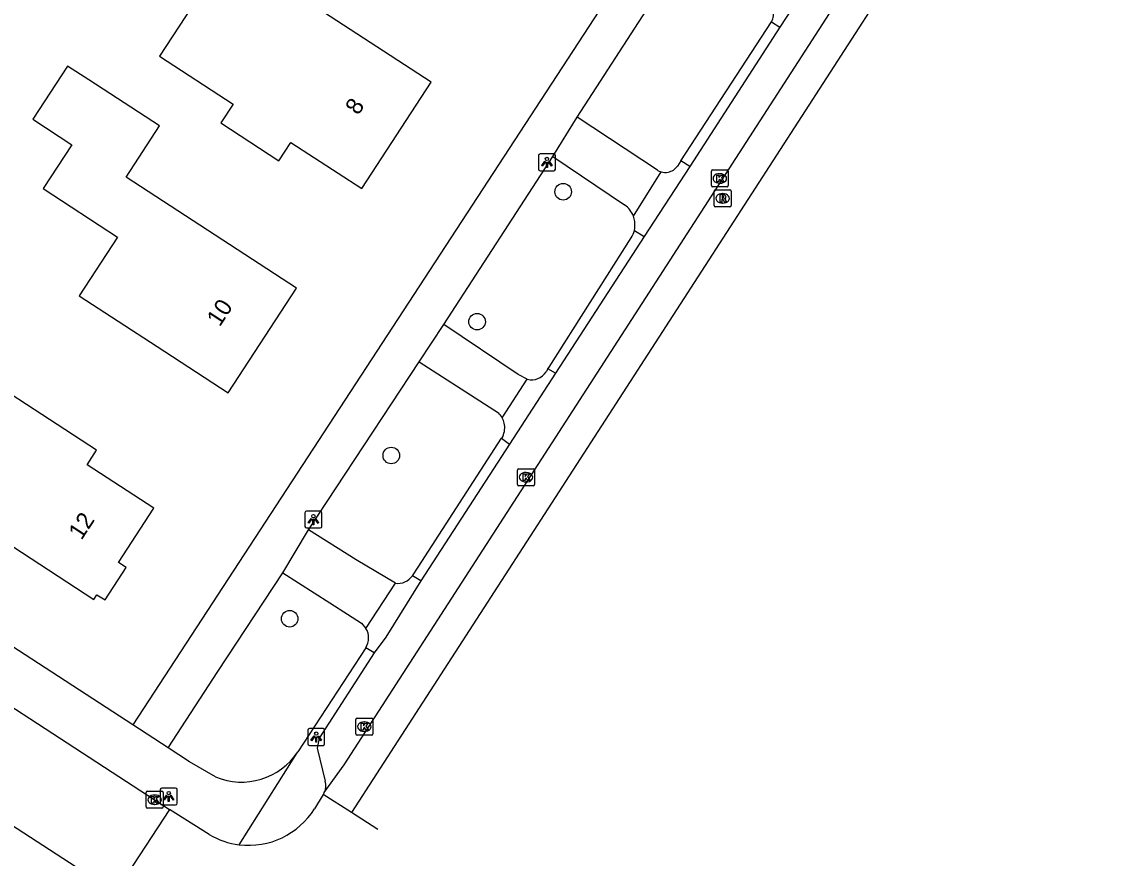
# Model space of a CAD drawing. Extents: x 161141 to 161601, y 381708 to 382245.
# Drawn here: x 161516.9 to 161581.4, y 382033 to 382082.4 of the extents above; entities that cross this region are included whole.
import ezdxf

# ---------------------------------------------------------------- set-up
doc = ezdxf.new("R2010")
doc.units = 0
for name, color, linetype in [('IMGEO_Boom', 7, 'Continuous'), ('IMGEO_Kolk', 7, 'Continuous'), ('IMGEO_Lichtpunt', 7, 'Continuous'), ('IMGEO_Pand', 7, 'Continuous'), ('IMGEO_Pand_nummerreeks', 7, 'Continuous'), ('IMGEO_Rijbaan_lokaal_gesloten', 7, 'Continuous'), ('IMGEO_Rijbaan_lokaal_open', 7, 'Continuous'), ('IMGEO_Rioolput', 7, 'Continuous'), ('IMGEO_Voetpad_open', 7, 'Continuous')]:
    doc.layers.add(name, color=color, linetype=linetype)

msp = doc.modelspace()

# ---------------------------------------------------------------- linework, layer by layer
at = {"layer": 'IMGEO_Boom'}
for centre in [(161548.856, 382072.342), (161543.772, 382064.666), (161538.702, 382056.761), (161532.7, 382047.114)]:
    msp.add_circle(centre, 0.489, dxfattribs=at)
at = {"layer": 'IMGEO_Kolk'}
for p, q in [((161557.611, 382072.704), (161557.611, 382073.556)), ((161557.686, 382073.63), (161558.538, 382073.63)), ((161558.612, 382073.556), (161558.612, 382072.704)), ((161558.122, 382072.85), (161558.097, 382072.85)), ((161558.099, 382073.41), (161558.124, 382073.41)), ((161558.538, 382072.63), (161557.686, 382072.63)), ((161546.165, 382055.049), (161546.165, 382055.901)), ((161546.24, 382055.975), (161547.092, 382055.975)), ((161546.653, 382055.755), (161546.678, 382055.755)), ((161547.166, 382055.901), (161547.166, 382055.049)), ((161547.092, 382054.975), (161546.24, 382054.975)), ((161546.676, 382055.195), (161546.651, 382055.195)), ((161536.682, 382041.24), (161537.534, 382041.24)), ((161536.607, 382040.314), (161536.607, 382041.166)), ((161537.095, 382041.02), (161537.12, 382041.02)), ((161537.608, 382041.166), (161537.608, 382040.314)), ((161537.534, 382040.24), (161536.682, 382040.24)), ((161537.118, 382040.46), (161537.093, 382040.46)), ((161524.224, 382035.995), (161524.224, 382036.847)), ((161524.299, 382036.921), (161525.151, 382036.921)), ((161524.712, 382036.701), (161524.737, 382036.701)), ((161525.225, 382036.847), (161525.225, 382035.995)), ((161524.735, 382036.141), (161524.71, 382036.141)), ((161525.151, 382035.921), (161524.299, 382035.921))]:
    msp.add_line(p, q, dxfattribs=at)
for points in [[(161557.611, 382072.704), (161557.611, 382073.556)], [(161557.686, 382073.63), (161558.538, 382073.63)], [(161558.612, 382073.556), (161558.612, 382072.704)], [(161557.932, 382073.33), (161558.055, 382073.33), (161558.055, 382073.179), (161558.185, 382073.33), (161558.349, 382073.33), (161558.203, 382073.179), (161558.356, 382072.93), (161558.204, 382072.93), (161558.119, 382073.094), (161558.055, 382073.027), (161558.055, 382072.93), (161557.932, 382072.93), (161557.932, 382073.33)], [(161558.538, 382072.63), (161557.686, 382072.63)], [(161546.165, 382055.049), (161546.165, 382055.901)], [(161546.24, 382055.975), (161547.092, 382055.975)], [(161546.486, 382055.675), (161546.609, 382055.675), (161546.609, 382055.524), (161546.739, 382055.675), (161546.903, 382055.675), (161546.757, 382055.524), (161546.91, 382055.275), (161546.758, 382055.275), (161546.673, 382055.439), (161546.609, 382055.372), (161546.609, 382055.275), (161546.486, 382055.275), (161546.486, 382055.675)], [(161547.166, 382055.901), (161547.166, 382055.049)], [(161547.092, 382054.975), (161546.24, 382054.975)], [(161536.682, 382041.24), (161537.534, 382041.24)], [(161536.607, 382040.314), (161536.607, 382041.166)], [(161536.928, 382040.94), (161537.051, 382040.94), (161537.051, 382040.789), (161537.181, 382040.94), (161537.345, 382040.94), (161537.199, 382040.789), (161537.352, 382040.54), (161537.2, 382040.54), (161537.115, 382040.704), (161537.051, 382040.637), (161537.051, 382040.54), (161536.928, 382040.54), (161536.928, 382040.94)], [(161537.608, 382041.166), (161537.608, 382040.314)], [(161537.534, 382040.24), (161536.682, 382040.24)], [(161524.224, 382035.995), (161524.224, 382036.847)], [(161524.299, 382036.921), (161525.151, 382036.921)], [(161525.225, 382036.847), (161525.225, 382035.995)], [(161524.545, 382036.621), (161524.668, 382036.621), (161524.668, 382036.47), (161524.798, 382036.621), (161524.962, 382036.621), (161524.816, 382036.47), (161524.969, 382036.221), (161524.817, 382036.221), (161524.732, 382036.385), (161524.668, 382036.318), (161524.668, 382036.221), (161524.545, 382036.221), (161524.545, 382036.621)], [(161525.151, 382035.921), (161524.299, 382035.921)]]:
    msp.add_lwpolyline(points, dxfattribs=at)
for centre, start, end in [((161557.688, 382073.554), 91.55205, 178.44795), ((161557.688, 382073.554), 91.55205, 178.44795), ((161558.536, 382073.554), 1.55205, 88.44795), ((161558.536, 382073.554), 1.55205, 88.44795), ((161557.688, 382072.706), 181.55205, 268.44795), ((161557.688, 382072.706), 181.55205, 268.44795), ((161558.536, 382072.706), 271.55205, 358.44795), ((161558.536, 382072.706), 271.55205, 358.44795), ((161546.242, 382055.899), 91.55205, 178.44795), ((161546.242, 382055.899), 91.55205, 178.44795), ((161547.09, 382055.899), 1.55205, 88.44795), ((161547.09, 382055.899), 1.55205, 88.44795), ((161546.242, 382055.051), 181.55205, 268.44795), ((161546.242, 382055.051), 181.55205, 268.44795), ((161547.09, 382055.051), 271.55205, 358.44795), ((161547.09, 382055.051), 271.55205, 358.44795), ((161536.684, 382041.164), 91.55205, 178.44795), ((161536.684, 382041.164), 91.55205, 178.44795), ((161537.532, 382041.164), 1.55205, 88.44795), ((161537.532, 382041.164), 1.55205, 88.44795), ((161536.684, 382040.316), 181.55205, 268.44795), ((161536.684, 382040.316), 181.55205, 268.44795), ((161537.532, 382040.316), 271.55205, 358.44795), ((161537.532, 382040.316), 271.55205, 358.44795), ((161524.301, 382036.845), 91.55205, 178.44795), ((161524.301, 382036.845), 91.55205, 178.44795), ((161525.149, 382036.845), 1.55205, 88.44795), ((161525.149, 382036.845), 1.55205, 88.44795), ((161524.301, 382035.997), 181.55205, 268.44795), ((161524.301, 382035.997), 181.55205, 268.44795), ((161525.149, 382035.997), 271.55205, 358.44795), ((161525.149, 382035.997), 271.55205, 358.44795)]:
    msp.add_arc(centre, 0.0765, start, end, dxfattribs=at)
for centre, major_axis, ratio, start_param, end_param in [((161558.098, 382073.13), (-0.387, 0.002), 0.722429, 4.712389, 7.853982), ((161558.123, 382073.13), (-0.39, 0.002), 0.717154, 1.570796, 4.712389), ((161546.652, 382055.475), (-0.387, 0.002), 0.722429, 4.712389, 7.853982), ((161546.677, 382055.475), (-0.39, 0.002), 0.717154, 1.570796, 4.712389), ((161537.094, 382040.74), (-0.387, 0.002), 0.722429, 4.712389, 7.853982), ((161537.119, 382040.74), (-0.39, 0.002), 0.717154, 1.570796, 4.712389), ((161524.711, 382036.421), (-0.387, 0.002), 0.722429, 4.712389, 7.853982), ((161524.736, 382036.421), (-0.39, 0.002), 0.717154, 1.570796, 4.712389)]:
    msp.add_ellipse(centre, major_axis=major_axis, ratio=ratio, start_param=start_param, end_param=end_param, dxfattribs=at)
at = {"layer": 'IMGEO_Lichtpunt'}
for p, q in [((161547.401, 382074.484), (161547.401, 382073.677)), ((161547.401, 382074.484), (161547.401, 382073.677)), ((161548.303, 382074.579), (161547.495, 382074.579)), ((161548.303, 382074.579), (161547.495, 382074.579)), ((161548.397, 382073.677), (161548.397, 382074.484)), ((161548.397, 382073.677), (161548.397, 382074.484)), ((161547.495, 382073.583), (161548.303, 382073.583)), ((161547.495, 382073.583), (161548.303, 382073.583)), ((161534.503, 382053.473), (161533.695, 382053.473)), ((161534.503, 382053.473), (161533.695, 382053.473)), ((161533.601, 382053.378), (161533.601, 382052.571)), ((161533.601, 382053.378), (161533.601, 382052.571)), ((161534.597, 382052.571), (161534.597, 382053.378)), ((161534.597, 382052.571), (161534.597, 382053.378)), ((161533.695, 382052.477), (161534.503, 382052.477)), ((161533.695, 382052.477), (161534.503, 382052.477)), ((161533.768, 382040.53), (161533.768, 382039.723)), ((161533.768, 382040.53), (161533.768, 382039.723)), ((161534.67, 382040.625), (161533.862, 382040.625)), ((161534.67, 382040.625), (161533.862, 382040.625)), ((161534.764, 382039.723), (161534.764, 382040.53)), ((161534.764, 382039.723), (161534.764, 382040.53)), ((161533.862, 382039.629), (161534.67, 382039.629)), ((161533.862, 382039.629), (161534.67, 382039.629)), ((161525.054, 382037.019), (161525.054, 382036.212)), ((161525.054, 382037.019), (161525.054, 382036.212)), ((161525.956, 382037.114), (161525.148, 382037.114)), ((161525.956, 382037.114), (161525.148, 382037.114)), ((161526.05, 382036.212), (161526.05, 382037.019)), ((161526.05, 382036.212), (161526.05, 382037.019)), ((161525.148, 382036.118), (161525.956, 382036.118)), ((161525.148, 382036.118), (161525.956, 382036.118))]:
    msp.add_line(p, q, dxfattribs=at)
for points in [[(161547.775, 382074.148), (161547.814, 382074.12), (161547.626, 382073.858), (161547.588, 382073.885), (161547.775, 382074.148)], [(161547.877, 382074.1), (161547.924, 382074.1), (161547.924, 382073.778), (161547.877, 382073.778), (161547.877, 382074.1)], [(161547.987, 382074.12), (161548.025, 382074.147), (161548.212, 382073.885), (161548.173, 382073.857), (161547.987, 382074.12)], [(161533.975, 382053.042), (161534.014, 382053.014), (161533.826, 382052.752), (161533.788, 382052.779), (161533.975, 382053.042)], [(161534.077, 382052.994), (161534.124, 382052.994), (161534.124, 382052.672), (161534.077, 382052.672), (161534.077, 382052.994)], [(161534.187, 382053.014), (161534.225, 382053.041), (161534.412, 382052.779), (161534.373, 382052.751), (161534.187, 382053.014)], [(161534.142, 382040.194), (161534.181, 382040.166), (161533.993, 382039.904), (161533.955, 382039.931), (161534.142, 382040.194)], [(161534.244, 382040.146), (161534.291, 382040.146), (161534.291, 382039.824), (161534.244, 382039.824), (161534.244, 382040.146)], [(161534.354, 382040.166), (161534.392, 382040.193), (161534.579, 382039.931), (161534.54, 382039.903), (161534.354, 382040.166)], [(161525.428, 382036.683), (161525.467, 382036.655), (161525.279, 382036.393), (161525.241, 382036.42), (161525.428, 382036.683)], [(161525.64, 382036.655), (161525.678, 382036.682), (161525.865, 382036.42), (161525.826, 382036.392), (161525.64, 382036.655)], [(161525.53, 382036.635), (161525.577, 382036.635), (161525.577, 382036.313), (161525.53, 382036.313), (161525.53, 382036.635)]]:
    msp.add_lwpolyline(points, dxfattribs=at)
for centre in [(161547.9, 382074.282), (161534.1, 382053.176), (161534.267, 382040.328), (161525.553, 382036.817)]:
    msp.add_circle(centre, 0.0994, dxfattribs=at)
for centre, start, end in [((161547.495, 382074.484), 90, 180), ((161547.495, 382074.484), 90, 180), ((161548.303, 382074.484), 0, 90), ((161548.303, 382074.484), 0, 90), ((161547.495, 382073.677), 180, 270), ((161547.495, 382073.677), 180, 270), ((161548.303, 382073.677), 270, 0), ((161548.303, 382073.677), 270, 360), ((161533.695, 382053.378), 90, 180), ((161533.695, 382053.378), 90, 180), ((161534.503, 382053.378), 0, 90), ((161534.503, 382053.378), 0, 90), ((161533.695, 382052.571), 180, 270), ((161533.695, 382052.571), 180, 270), ((161534.503, 382052.571), 270, 0), ((161534.503, 382052.571), 270, 360), ((161533.862, 382040.53), 90, 180), ((161533.862, 382040.53), 90, 180), ((161534.67, 382040.53), 0, 90), ((161534.67, 382040.53), 0, 90), ((161533.862, 382039.723), 180, 270), ((161533.862, 382039.723), 180, 270), ((161534.67, 382039.723), 270, 0), ((161534.67, 382039.723), 270, 360), ((161525.148, 382037.019), 90, 180), ((161525.148, 382037.019), 90, 180), ((161525.956, 382037.019), 0, 90), ((161525.956, 382037.019), 0, 90), ((161525.148, 382036.212), 180, 270), ((161525.148, 382036.212), 180, 270), ((161525.956, 382036.212), 270, 0), ((161525.956, 382036.212), 270, 360)]:
    msp.add_arc(centre, 0.0946, start, end, dxfattribs=at)
at = {"layer": 'IMGEO_Pand'}
for points in [[(161525.007, 382080.354), (161529.353, 382077.522), (161528.63, 382076.412), (161532.059, 382074.178), (161532.764, 382075.259), (161536.96, 382072.525), (161541.06, 382078.818), (161527.88, 382087.405), (161529.841, 382090.414), (161525.651, 382093.143), (161524.545, 382093.864), (161521.198, 382088.726), (161527.701, 382084.489), (161525.007, 382080.354)], [(161524.873, 382063.195), (161529.061, 382060.463), (161533.095, 382066.653), (161523.049, 382073.199), (161525.013, 382076.229), (161520.824, 382078.958), (161519.575, 382079.772), (161517.521, 382076.623), (161519.823, 382075.12), (161518.135, 382072.533), (161522.531, 382069.665), (161520.269, 382066.197), (161524.873, 382063.195)], [(161512.023, 382063.108), (161513.814, 382065.857), (161508.368, 382069.406), (161505.406, 382071.336), (161502.144, 382066.33), (161505.105, 382064.4), (161504.545, 382063.541), (161509.99, 382059.992), (161510.091, 382060.146), (161511.727, 382059.08), (161510.877, 382057.775), (161513.345, 382056.167), (161512.05, 382054.18), (161521.136, 382048.26), (161521.315, 382048.534), (161521.792, 382048.223), (161523.042, 382050.142), (161522.592, 382050.435), (161524.682, 382053.642), (161520.733, 382056.215), (161521.288, 382057.068), (161512.023, 382063.108)]]:
    msp.add_lwpolyline(points, dxfattribs=at)
at = {"layer": 'IMGEO_Rijbaan_lokaal_gesloten'}
for points in [[(161534.744, 382036.848), (161535.916, 382038.476), (161568.691, 382089.227), (161572.916, 382096.506)], [(161571.794, 382090.515), (161536.35, 382035.66)], [(161534.744, 382036.848), (161534.678, 382036.739)]]:
    msp.add_lwpolyline(points, dxfattribs=at)
at = {"layer": 'IMGEO_Rijbaan_lokaal_open'}
for points in [[(161385.362, 382126.757), (161388.136, 382124.895), (161391.361, 382122.845), (161399.992, 382117.288), (161403.197, 382115.21), (161416.21, 382106.739), (161420.597, 382103.968), (161426.931, 382099.82), (161440.905, 382090.804), (161444.055, 382088.754), (161453.24, 382082.778), (161460.192, 382078.284), (161467.324, 382073.702), (161468.287, 382073.003), (161471.488, 382070.983), (161480.028, 382065.466), (161483.251, 382063.426), (161485.554, 382061.86), (161494.669, 382055.998), (161498.469, 382053.534), (161512.078, 382044.654), (161521.765, 382038.348), (161525.596, 382035.854)], [(161522.385, 382030.943), (161510.796, 382038.454)], [(161534.678, 382036.739), (161534.166, 382035.893)], [(161536.35, 382035.66), (161534.678, 382036.739)], [(161525.596, 382035.854), (161522.385, 382030.943)], [(161527.949, 382034.358), (161525.596, 382035.854)], [(161537.898, 382034.67), (161536.35, 382035.66)]]:
    msp.add_lwpolyline(points, dxfattribs=at)
for centre, radius, start, end in [((161530.271, 382038.316), 4.587, 263.08011, 328.11728), ((161530.267, 382038.315), 4.586, 239.63862, 263.12265)]:
    msp.add_arc(centre, radius, start, end, dxfattribs=at)
at = {"layer": 'IMGEO_Rioolput'}
for p, q in [((161557.783, 382071.527), (161557.783, 382072.379)), ((161557.858, 382072.453), (161558.71, 382072.453)), ((161558.271, 382072.233), (161558.296, 382072.233)), ((161558.784, 382072.379), (161558.784, 382071.527)), ((161558.294, 382071.673), (161558.269, 382071.673)), ((161558.71, 382071.453), (161557.858, 382071.453))]:
    msp.add_line(p, q, dxfattribs=at)
for points in [[(161557.783, 382071.527), (161557.783, 382072.379)], [(161557.858, 382072.453), (161558.71, 382072.453)], [(161558.372, 382072.151), (161558.12, 382072.153), (161558.12, 382071.753)], [(161558.784, 382072.379), (161558.784, 382071.527)], [(161558.12, 382071.753), (161558.244, 382071.753), (161558.244, 382071.915), (161558.255, 382071.915)], [(161558.298, 382072.072), (161558.244, 382072.072), (161558.244, 382071.991)], [(161558.244, 382071.991), (161558.296, 382071.991)], [(161558.302, 382071.886), (161558.373, 382071.753), (161558.513, 382071.753), (161558.448, 382071.879)], [(161558.71, 382071.453), (161557.858, 382071.453)]]:
    msp.add_lwpolyline(points, dxfattribs=at)
for centre, radius, start, end in [((161557.86, 382072.377), 0.0765, 91.55205, 178.44795), ((161557.86, 382072.377), 0.0765, 91.55205, 178.44795), ((161558.371, 382072.041), 0.109, 350.36119, 89.41601), ((161558.708, 382072.377), 0.0765, 1.55205, 88.44795), ((161558.708, 382072.377), 0.0765, 1.55205, 88.44795), ((161557.86, 382071.529), 0.0765, 181.55205, 268.44795), ((161557.86, 382071.529), 0.0765, 181.55205, 268.44795), ((161558.254, 382071.862), 0.0533, 26.02933, 88.69889), ((161558.28, 382072.18), 0.19, 274.7715, 282.96867), ((161558.304, 382071.976), 0.0964, 77.00612, 93.18647), ((161558.318, 382072.033), 0.0378, 276.66336, 79.67722), ((161558.369, 382072.041), 0.112, 277.58423, 350.98172), ((161558.353, 382071.826), 0.108, 29.51342, 73.79051), ((161558.708, 382071.529), 0.0765, 271.55205, 358.44795), ((161558.708, 382071.529), 0.0765, 271.55205, 358.44795)]:
    msp.add_arc(centre, radius, start, end, dxfattribs=at)
for centre, major_axis, ratio, start_param, end_param in [((161558.27, 382071.953), (-0.387, 0.002), 0.722429, 4.712389, 7.853982), ((161558.295, 382071.953), (-0.39, 0.002), 0.717154, 1.570796, 4.712389)]:
    msp.add_ellipse(centre, major_axis=major_axis, ratio=ratio, start_param=start_param, end_param=end_param, dxfattribs=at)
at = {"layer": 'IMGEO_Voetpad_open'}
for points in [[(161523.437, 382040.853), (161500, 382056.07), (161450.498, 382088.211), (161408.789, 382114.947), (161389.855, 382127.317), (161365.175, 382143.293), (161365.084, 382143.565)], [(161581.409, 382129.761), (161561.628, 382099.383), (161523.437, 382040.853)], [(161549.678, 382076.751), (161556.061, 382086.613)], [(161564.239, 382086.032), (161561.667, 382082.065)], [(161555.805, 382074.166), (161561.16, 382082.381)], [(161561.667, 382082.065), (161556.335, 382073.842)], [(161561.16, 382082.381), (161561.667, 382082.065)], [(161548.238, 382074.428), (161549.678, 382076.751)], [(161554.422, 382073.613), (161549.678, 382076.751)], [(161541.805, 382064.505), (161548.238, 382074.428)], [(161548.238, 382074.428), (161552.488, 382071.564)], [(161555.805, 382074.166), (161555.605, 382073.86)], [(161556.335, 382073.842), (161555.805, 382074.166)], [(161553.007, 382070.898), (161554.64, 382073.517)], [(161556.335, 382073.842), (161553.645, 382069.693)], [(161547.959, 382061.886), (161548.022, 382061.982), (161552.884, 382069.618)], [(161553.645, 382069.693), (161548.411, 382061.62)], [(161553.065, 382070.06), (161553.645, 382069.693)], [(161540.355, 382062.295), (161541.805, 382064.505)], [(161546.737, 382061.267), (161546.19, 382061.555), (161541.805, 382064.505)], [(161533.813, 382052.367), (161540.355, 382062.295)], [(161540.355, 382062.295), (161545.028, 382059.277)], [(161547.959, 382061.886), (161547.846, 382061.711)], [(161548.411, 382061.62), (161547.959, 382061.886)], [(161545.258, 382058.983), (161546.737, 382061.267)], [(161548.411, 382061.62), (161545.69, 382057.424)], [(161539.95, 382049.657), (161540.282, 382050.166), (161545.221, 382057.781)], [(161545.69, 382057.424), (161540.456, 382049.35)], [(161545.289, 382057.886), (161545.221, 382057.781)], [(161545.221, 382057.781), (161545.69, 382057.424)], [(161532.291, 382049.829), (161533.813, 382052.367)], [(161538.946, 382049.208), (161536.622, 382050.604), (161533.813, 382052.367)], [(161525.518, 382039.495), (161528.456, 382043.995), (161532.291, 382049.829)], [(161532.291, 382049.829), (161535.064, 382048.048), (161536.938, 382046.844), (161537.207, 382046.547)], [(161540.456, 382049.35), (161539.95, 382049.657)], [(161537.207, 382046.547), (161538.946, 382049.208)], [(161540.456, 382049.35), (161538.374, 382046.036), (161537.696, 382045.093)], [(161537.192, 382045.404), (161533.184, 382039.253)], [(161537.696, 382045.093), (161534.437, 382040.067), (161534.33, 382039.471), (161534.799, 382037.517)], [(161537.696, 382045.093), (161537.192, 382045.404)], [(161525.518, 382039.495), (161523.437, 382040.853)], [(161528.309, 382037.772), (161526.784, 382038.653), (161525.518, 382039.495)], [(161529.718, 382033.762), (161533.151, 382039.185), (161533.184, 382039.253)]]:
    msp.add_lwpolyline(points, dxfattribs=at)
for centre, radius, start, end in [((161560.344, 382082.836), 0.935, 330.87903, 17.06204), ((161554.905, 382074.414), 0.935, 238.91578, 253.55001), ((161554.881, 382074.367), 0.883, 254.13744, 281.46792), ((161554.889, 382074.356), 0.871, 281.1415, 325.31688), ((161551.671, 382070.392), 1.429, 20.73963, 55.11747), ((161551.663, 382070.381), 1.44, 7.97325, 21.03293), ((161551.615, 382070.388), 1.487, 347.26233, 7.46271), ((161551.649, 382070.382), 1.452, 328.26453, 347.19705), ((161546.998, 382062.222), 0.99, 254.73036, 328.90808), ((161544.234, 382058.419), 1.169, 28.84853, 47.22454), ((161544.246, 382058.412), 1.162, 13.02195, 29.42536), ((161544.201, 382058.408), 1.207, 334.38025, 12.73192), ((161539.075, 382050.267), 1.067, 263.0652, 325.12425), ((161536.289, 382045.987), 1.075, 327.13152, 31.36474), ((161529.854, 382041.45), 3.989, 247.21393, 326.58309), ((161533.989, 382037.247), 0.854, 332.15727, 18.44304)]:
    msp.add_arc(centre, radius, start, end, dxfattribs=at)

# ---------------------------------------------------------------- texts
at = {"layer": 'IMGEO_Pand_nummerreeks'}
for s, rotation, p in [('8', 56.91505, (161536.75, 382076.82)), ('10', 56.90786, (161528.566, 382064.32)), ('12', 56.61969, (161520.398, 382051.721))]:
    msp.add_text(s, height=1, rotation=rotation, dxfattribs=at).set_placement(p)

doc.saveas('drawing.dxf')
